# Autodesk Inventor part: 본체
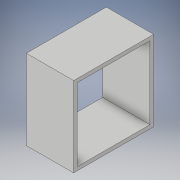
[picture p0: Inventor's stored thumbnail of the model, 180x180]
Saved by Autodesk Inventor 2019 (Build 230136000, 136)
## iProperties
Created: 2022-03
Part Number: 본체
Material: 일반
Document SubType Name: Modeling
Designer: LINE501-3
Density: 1 g/cm^3
Appearance: 기본값
Author: LINE501-3
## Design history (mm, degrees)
sketch "스케치1"
  geometry: L1 (-55, 55)-(55, 55); L2 (55, 55)-(55, -55); L3 (55, -55)-(-55, -55); L4 (-55, -55)-(-55, 55); L5 (-55, 55)-(55, -55); L6 (55, 55)-(-55, -55); L7 (-50, 50)-(50, 50); L8 (50, 50)-(50, -50); L9 (50, -50)-(-50, -50); L10 (-50, -50)-(-50, 50); L11 (-50, 50)-(50, -50); L12 (50, 50)-(-50, -50); 2 further points
  constraints: 24 end point, 5 midpoint, 4 parallel, 2 horizontal, 2 perpendicular, 1 other
  dimensions: "d8" = 110 distance of L2.end L3.end; "d9" = 110 distance of L1.end L2.end; "d10" = 100 distance of L8.end L9.end; "d11" = 100 distance of L7.end L8.end
extrude "돌출1" new body sketch "스케치1" distance "d12" = 65; taper "d13" = 0 deg
node "솔리드1"
